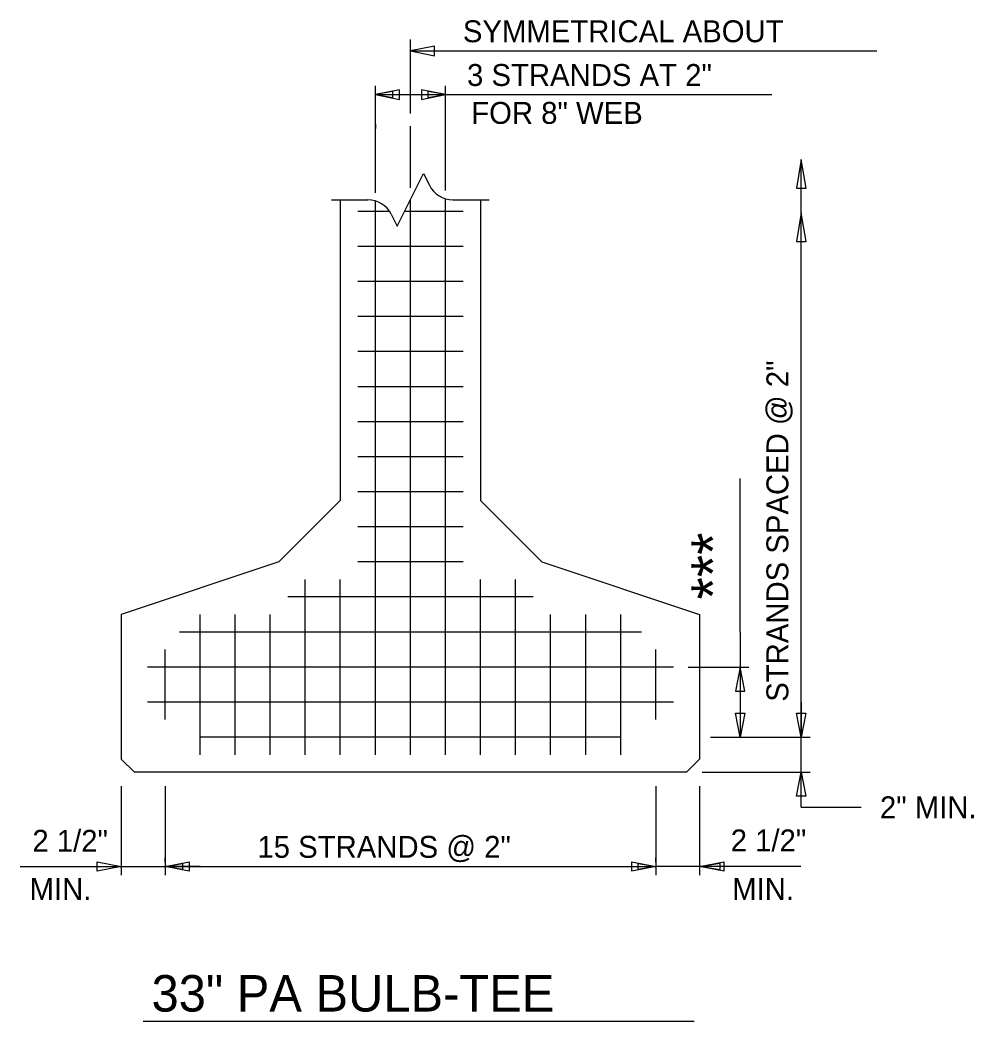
# Model space of a CAD drawing. Extents: x 637933 to 640019, y 298854 to 300042.
# Drawn here: x 639229.5 to 639360.2, y 299746.8 to 299883.9 of the extents above; entities that cross this region are included whole.
import ezdxf

# ---------------------------------------------------------------- set-up
doc = ezdxf.new("R2010")
doc.units = 0
doc.layers.add('1', color=7, linetype='Continuous')
doc.layers.add('3', color=7, linetype='Continuous')

# ---------------------------------------------------------------- blocks, each defined once
blk = doc.blocks.new('SA')
at = {"layer": '3'}
blk.add_lwpolyline([(1.143, -0.1905), (1.143, 0.1905), (0, 0), (0, 0)], close=True, dxfattribs=at)

msp = doc.modelspace()

# ---------------------------------------------------------------- linework, layer by layer
at = {"layer": '1'}
for p, q in [((639283, 299871.12), (639283, 299881.23)), ((639283, 299879.67), (639346.85, 299879.67)), ((639278.2, 299860.25), (639278.2, 299874.89)), ((639287.8, 299860.55), (639287.8, 299874.89)), ((639278.2, 299873.69), (639287.8, 299873.69)), ((639287.8, 299873.69), (639332.46, 299873.69)), ((639278.2, 299869.64), (639278.2, 299869.04)), ((639283, 299860.93), (639283, 299869.36)), ((639336.51, 299785.68), (639336.51, 299864.82)), ((639273.4, 299859.28), (639273.4, 299818.08)), ((639278.2, 299783.28), (639278.2, 299859.12)), ((639283, 299783.28), (639283, 299859.31)), ((639287.8, 299783.28), (639287.8, 299859.42)), ((639292.6, 299859.28), (639292.6, 299818.08)), ((639280.15, 299857.68), (639275.8, 299857.68)), ((639290.2, 299857.68), (639282.19, 299857.68)), ((639290.2, 299852.88), (639275.8, 299852.88)), ((639290.2, 299848.08), (639275.8, 299848.08)), ((639290.2, 299843.28), (639275.8, 299843.28)), ((639290.2, 299838.48), (639275.8, 299838.48)), ((639290.2, 299833.68), (639275.8, 299833.68)), ((639290.2, 299828.88), (639275.8, 299828.88)), ((639290.2, 299824.08), (639275.8, 299824.08)), ((639328.15, 299800.08), (639328.15, 299821.1)), ((639290.2, 299819.28), (639275.8, 299819.28)), ((639273.4, 299818.08), (639265, 299809.68)), ((639292.6, 299818.08), (639301, 299809.68)), ((639290.2, 299814.48), (639275.8, 299814.48)), ((639265, 299809.68), (639243.4, 299802.48)), ((639290.21, 299809.68), (639275.79, 299809.68)), ((639301, 299809.68), (639322.6, 299802.48)), ((639268.6, 299783.28), (639268.6, 299807.28)), ((639273.4, 299783.28), (639273.4, 299807.28)), ((639292.6, 299783.28), (639292.6, 299807.28)), ((639297.4, 299783.28), (639297.4, 299807.28)), ((639299.8, 299804.88), (639266.2, 299804.88)), ((639243.4, 299802.48), (639243.4, 299782.68)), ((639254.2, 299783.28), (639254.2, 299802.48)), ((639259, 299783.28), (639259, 299802.48)), ((639263.8, 299783.28), (639263.8, 299802.48)), ((639302.2, 299783.28), (639302.2, 299802.48)), ((639307, 299783.28), (639307, 299802.48)), ((639311.8, 299783.28), (639311.8, 299802.48)), ((639322.6, 299802.48), (639322.6, 299782.68)), ((639314.62, 299800.08), (639251.38, 299800.08)), ((639328.15, 299800.08), (639328.15, 299785.68)), ((639249.4, 299788.08), (639249.4, 299797.68)), ((639316.6, 299788.08), (639316.6, 299797.68)), ((639319, 299795.28), (639247, 299795.28)), ((639321.03, 299795.28), (639329.35, 299795.28)), ((639319, 299790.48), (639247, 299790.48)), ((639336.51, 299790.48), (639336.51, 299785.68)), ((639311.8, 299785.68), (639254.2, 299785.68)), ((639324.1, 299785.68), (639337.71, 299785.68)), ((639336.51, 299780.88), (639336.51, 299785.68)), ((639245.2, 299780.88), (639243.4, 299782.68)), ((639320.8, 299780.88), (639322.6, 299782.68)), ((639320.8, 299780.88), (639245.2, 299780.88)), ((639322.92, 299780.88), (639337.71, 299780.88)), ((639336.51, 299776.08), (639336.51, 299780.88)), ((639243.4, 299778.98), (639243.4, 299766.77)), ((639249.4, 299778.98), (639249.4, 299766.77)), ((639316.6, 299778.98), (639316.6, 299766.77)), ((639322.6, 299778.98), (639322.6, 299766.77)), ((639336.51, 299776.08), (639344.71, 299776.08)), ((639229.55, 299767.97), (639243.4, 299767.97)), ((639243.4, 299767.97), (639249.4, 299767.97)), ((639249.4, 299768.57), (639249.4, 299769.17)), ((639254.2, 299767.97), (639249.4, 299767.97)), ((639249.4, 299767.97), (639316.6, 299767.97)), ((639311.8, 299767.97), (639316.6, 299767.97)), ((639316.6, 299768.57), (639316.6, 299769.17)), ((639322.6, 299767.97), (639316.6, 299767.97)), ((639336.46, 299767.97), (639322.6, 299767.97))]:
    msp.add_line(p, q, dxfattribs=at)
for points in [[(639286.3, 299880.33), (639283, 299879.67), (639286.3, 299879.01)], [(639281.5, 299874.35), (639278.2, 299873.69), (639281.5, 299873.03)], [(639280.6, 299874.09), (639278.2, 299873.69), (639280.6, 299873.29)], [(639284.5, 299873.03), (639287.8, 299873.69), (639284.5, 299874.35)], [(639285.4, 299873.29), (639287.8, 299873.69), (639285.4, 299874.09)], [(639328.79, 299791.98), (639328.15, 299795.28), (639327.51, 299791.98)], [(639328.79, 299788.98), (639328.15, 299785.68), (639327.51, 299788.98)], [(639337.15, 299788.98), (639336.51, 299785.68), (639335.87, 299788.98)], [(639335.87, 299777.58), (639336.51, 299780.88), (639337.15, 299777.58)], [(639240.1, 299768.61), (639243.4, 299767.97), (639240.1, 299767.33)], [(639252.7, 299767.33), (639249.4, 299767.97), (639252.7, 299768.61)], [(639251.8, 299767.57), (639249.4, 299767.97), (639251.8, 299768.37)], [(639313.3, 299768.61), (639316.6, 299767.97), (639313.3, 299767.33)], [(639314.2, 299768.37), (639316.6, 299767.97), (639314.2, 299767.57)], [(639325.9, 299767.33), (639322.6, 299767.97), (639325.9, 299768.61)], [(639325.35, 299767.51), (639322.6, 299767.97), (639325.35, 299768.43)]]:
    msp.add_lwpolyline(points, close=True, dxfattribs=at)
for points in [[(639280.38, 299857.29), (639281.19, 299855.68), (639284.79, 299862.88), (639285.59, 299861.27)], [(639272.2, 299859.28), (639277.16, 299859.28)], [(639288.81, 299859.28), (639293.8, 299859.28)], [(639246.39, 299746.81), (639321.87, 299746.81)]]:
    msp.add_lwpolyline(points, dxfattribs=at)
for centre, start, end in [((639288.81, 299862.88), 206.5651, 270), ((639277.16, 299855.68), 26.5651, 90)]:
    msp.add_arc(centre, 3.6, start, end, dxfattribs=at)

# ---------------------------------------------------------------- block references
at = {"layer": '1', "xscale": 3.4644969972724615, "yscale": 3.4644969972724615, "rotation": -90.00000000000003}
for p in [(639336.51, 299864.82), (639336.51, 299857.51)]:
    msp.add_blockref('SA', p, dxfattribs=at)

# ---------------------------------------------------------------- texts
at = {"layer": '1'}
for s, height, p in [('SYMMETRICAL ABOUT  ', 3, (639290.18, 299880.86)), ('3 STRANDS AT 2"', 3, (639290.75, 299874.87)), ('FOR 8" WEB', 3, (639291.32, 299869.68)), ('2 1/2"', 3, (639231.24, 299769.99)), ('15 STRANDS @ 2"', 3, (639262.05, 299769.16)), ('2 1/2"', 3, (639326.85, 299770.04)), ('33" PA BULB-TEE', 5, (639247.56, 299748.1))]:
    msp.add_text(s, height=height, dxfattribs=at).set_placement(p)
for s, height, rotation, p in [('STRANDS SPACED @ 2"', 3, 90, (639334.74, 299790.53)), ('***', 5.88, 90, (639327.36, 299804.53)), ('2" MIN.', 3, 360, (639347.28, 299774.58)), ('MIN.', 3, 360, (639230.86, 299763.38)), ('MIN.', 3, 360, (639327.05, 299763.39))]:
    msp.add_text(s, height=height, rotation=rotation, dxfattribs=at).set_placement(p)

doc.saveas('drawing.dxf')
